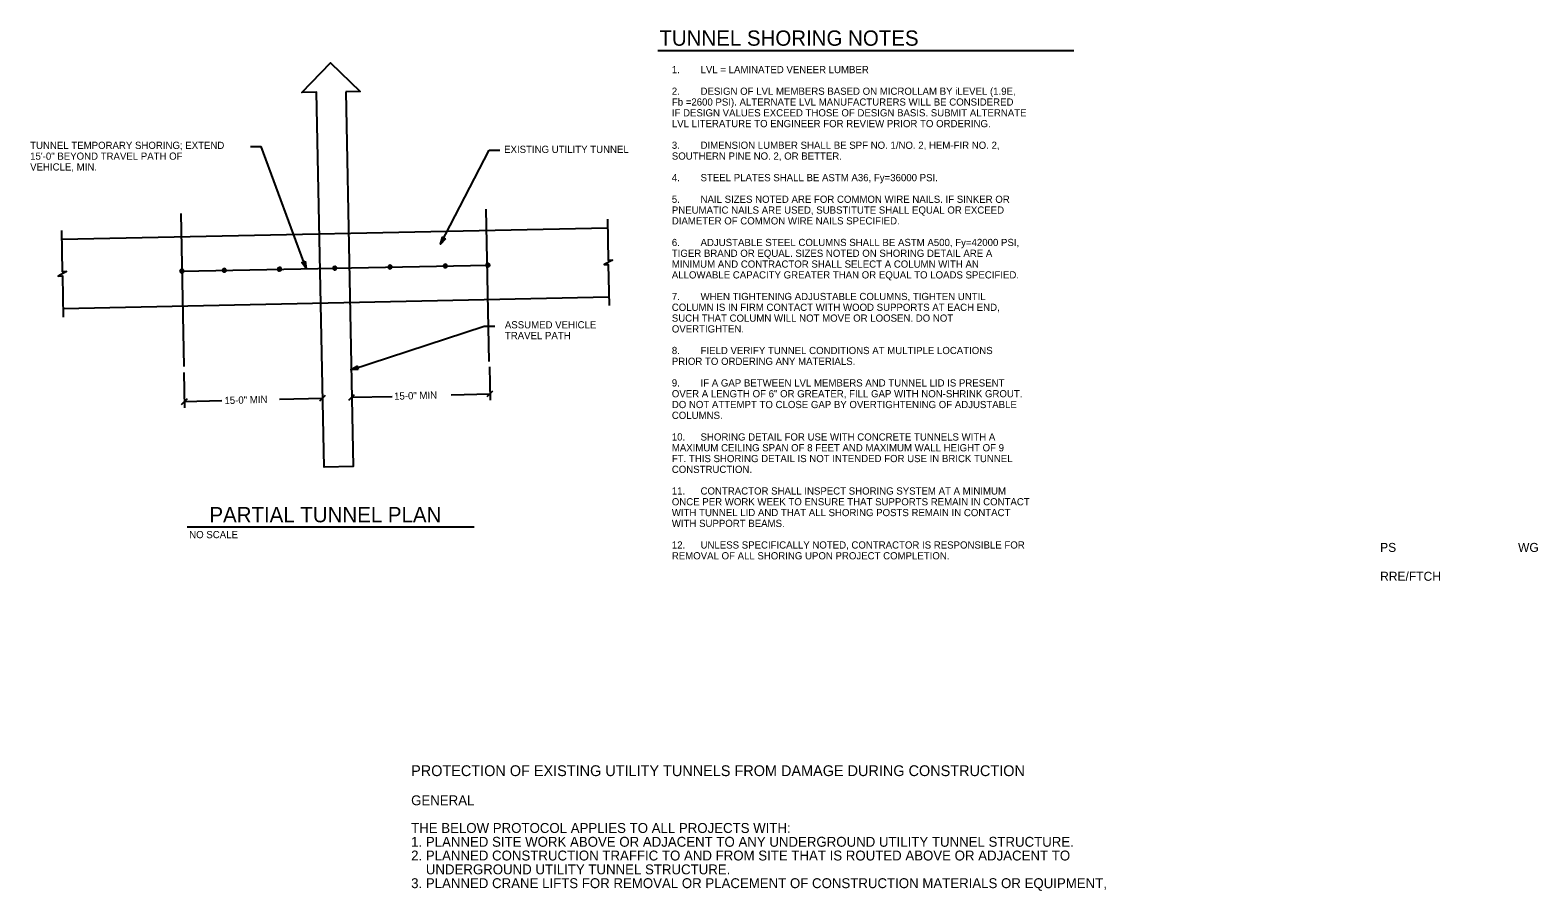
# Model space of a CAD drawing. Extents: x 10051 to 10282, y 10006 to 10178.
# Drawn here: x 10134.4 to 10274, y 10084.9 to 10164.6 of the extents above; entities that cross this region are included whole.
import ezdxf

# ---------------------------------------------------------------- set-up
doc = ezdxf.new("R2010")
doc.units = 0
for name, color, linetype in [('G-ANNO-CELL', 7, 'Continuous'), ('G-ANNO-TEXT', 7, 'Continuous'), ('G-DETL-LINE', 7, 'Continuous'), ('G-TITL-TEXT', 7, 'Continuous')]:
    doc.layers.add(name, color=color, linetype=linetype)

msp = doc.modelspace()

# ---------------------------------------------------------------- linework, layer by layer
at = {"layer": 'G-ANNO-CELL'}
for p, q in [((10192.53, 10162.71), (10231.05, 10162.71)), ((10148.96, 10118.6), (10175.54, 10118.6))]:
    msp.add_line(p, q, dxfattribs=at)
at = {"layer": 'G-ANNO-TEXT'}
for p, q in [((10154.81, 10153.83), (10155.81, 10153.83)), ((10159.96, 10142.51), (10155.81, 10153.83)), ((10172.42, 10144.76), (10176.91, 10153.49)), ((10176.91, 10153.49), (10177.91, 10153.49)), ((10148.36, 10147.6), (10148.64, 10133.45)), ((10176.93, 10133.92), (10176.65, 10148.02)), ((10164.1, 10133.13), (10176.44, 10137.17)), ((10176.44, 10137.17), (10177.44, 10137.17)), ((10176.94, 10133.42), (10177, 10130.34)), ((10148.65, 10132.9), (10148.71, 10129.63)), ((10148.44, 10129.95), (10148.97, 10130.48)), ((10157.51, 10130.43), (10161.5, 10130.53)), ((10161.23, 10130.27), (10161.76, 10130.8)), ((10163.93, 10130.34), (10164.46, 10130.87)), ((10164.19, 10130.6), (10167.93, 10130.69)), ((10173.4, 10130.83), (10176.99, 10130.92)), ((10176.73, 10130.66), (10177.26, 10131.19)), ((10148.7, 10130.21), (10152.17, 10130.3))]:
    msp.add_line(p, q, dxfattribs=at)
for points in [[(10172.88, 10145.27), (10172.42, 10144.76), (10172.58, 10145.42)], [(10159.89, 10143.19), (10159.96, 10142.51), (10159.57, 10143.08)], [(10164.78, 10133.18), (10164.1, 10133.13), (10164.68, 10133.49)]]:
    msp.add_lwpolyline(points, close=True, dxfattribs=at)
at = {"layer": 'G-DETL-LINE'}
msp.add_line((10148.46, 10142.28), (10176.75, 10142.84), dxfattribs=at)
for points in [[(10163.63, 10158.89), (10164.32, 10124.2), (10161.63, 10124.14), (10160.93, 10158.83), (10159.58, 10158.81), (10162.23, 10161.56), (10164.98, 10158.91), (10163.63, 10158.89)], [(10187.86, 10147.09), (10187.94, 10143.29), (10188.34, 10143.3), (10187.55, 10142.89), (10187.95, 10142.89), (10188.02, 10139.09)], [(10137.32, 10146.03), (10137.39, 10142.23), (10137.79, 10142.24), (10137, 10141.82), (10137.4, 10141.83), (10137.48, 10138.03)], [(10137.33, 10145.23), (10187.88, 10146.29)], [(10172.86, 10142.92), (10172.86, 10142.76), (10172.7, 10142.76)], [(10172.86, 10142.61), (10172.86, 10142.92), (10172.86, 10142.92)], [(10176.78, 10143), (10176.79, 10142.84), (10176.63, 10142.84)], [(10176.79, 10142.69), (10176.78, 10143), (10176.78, 10143)], [(10148.46, 10142.12), (10148.46, 10142.43), (10148.46, 10142.43)], [(10148.46, 10142.43), (10148.46, 10142.28), (10148.62, 10142.28)], [(10148.62, 10142.28), (10148.46, 10142.28), (10148.46, 10142.12)], [(10152.39, 10142.2), (10152.38, 10142.51), (10152.38, 10142.51)], [(10152.38, 10142.51), (10152.39, 10142.36), (10152.54, 10142.36)], [(10152.54, 10142.36), (10152.39, 10142.36), (10152.39, 10142.2)], [(10157.51, 10142.3), (10157.5, 10142.62), (10157.5, 10142.62)], [(10157.5, 10142.62), (10157.5, 10142.46), (10157.66, 10142.46)], [(10157.66, 10142.46), (10157.5, 10142.46), (10157.51, 10142.3)], [(10162.63, 10142.4), (10162.62, 10142.72), (10162.62, 10142.72)], [(10162.62, 10142.72), (10162.62, 10142.56), (10162.78, 10142.56)], [(10162.78, 10142.56), (10162.62, 10142.56), (10162.63, 10142.4)], [(10167.74, 10142.82), (10167.74, 10142.66), (10167.59, 10142.66)], [(10167.59, 10142.66), (10167.74, 10142.66), (10167.75, 10142.51)], [(10167.75, 10142.51), (10167.74, 10142.82), (10167.74, 10142.82)], [(10172.7, 10142.76), (10172.86, 10142.76), (10172.86, 10142.61)], [(10176.63, 10142.84), (10176.79, 10142.84), (10176.79, 10142.69)], [(10137.46, 10138.83), (10188.01, 10139.89)]]:
    msp.add_lwpolyline(points, dxfattribs=at)
for centre in [(10172.86, 10142.76), (10176.79, 10142.84), (10148.46, 10142.28), (10152.39, 10142.36), (10157.5, 10142.46), (10162.62, 10142.56), (10167.74, 10142.66)]:
    msp.add_circle(centre, 0.157, dxfattribs=at)
for centre, start, end in [((10172.86, 10142.76), 91.1419, 181.1419), ((10172.86, 10142.76), 1.1419, 91.1419), ((10176.79, 10142.84), 91.1419, 181.1419), ((10176.79, 10142.84), 1.1419, 91.1419), ((10148.46, 10142.28), 91.1419, 181.1419), ((10148.46, 10142.28), 181.1419, 271.1419), ((10148.46, 10142.28), 1.1419, 91.1419), ((10148.46, 10142.28), 271.1419, 1.1419), ((10152.39, 10142.36), 91.1419, 181.1419), ((10152.39, 10142.36), 181.1419, 271.1419), ((10152.39, 10142.36), 1.1419, 91.1419), ((10152.39, 10142.36), 271.1419, 1.1419), ((10157.5, 10142.46), 91.1419, 181.1419), ((10157.5, 10142.46), 181.1419, 271.1419), ((10157.5, 10142.46), 1.1419, 91.1419), ((10157.5, 10142.46), 271.1419, 1.1419), ((10162.62, 10142.56), 91.1419, 181.1419), ((10162.62, 10142.56), 181.1419, 271.1419), ((10162.62, 10142.56), 1.1419, 91.1419), ((10162.62, 10142.56), 271.1419, 1.1419), ((10167.74, 10142.66), 91.1419, 181.1419), ((10167.74, 10142.66), 181.1419, 271.1419), ((10167.74, 10142.66), 1.1419, 91.1419), ((10167.74, 10142.66), 271.1419, 1.1419), ((10172.86, 10142.76), 181.1419, 271.1419), ((10172.86, 10142.76), 271.1419, 1.1419), ((10176.79, 10142.84), 181.1419, 271.1419), ((10176.79, 10142.84), 271.1419, 1.1419)]:
    msp.add_arc(centre, 0.157, start, end, dxfattribs=at)

# ---------------------------------------------------------------- texts
at = {"layer": 'G-ANNO-CELL'}
for s, height, p in [('TUNNEL SHORING NOTES', 1.4167, (10192.68, 10163.14)), ('PARTIAL TUNNEL PLAN', 1.4167, (10151.01, 10119.03)), ('NO SCALE', 0.667, (10149.14, 10117.56))]:
    msp.add_text(s, height=height, dxfattribs=at).set_placement(p)
at = {"layer": 'G-ANNO-TEXT'}
for s, height, p in [('1.', 0.667, (10193.83, 10160.6)), ('LVL = LAMINATED VENEER LUMBER', 0.6667, (10196.49, 10160.6)), ('2.', 0.667, (10193.83, 10158.6)), ('Fb =2600 PSI). ALTERNATE LVL MANUFACTURERS WILL BE CONSIDERED ', 0.6667, (10193.83, 10157.6)), ('DESIGN OF LVL MEMBERS BASED ON MICROLLAM BY iLEVEL (1.9E, ', 0.6667, (10196.49, 10158.6)), ('IF DESIGN VALUES EXCEED THOSE OF DESIGN BASIS. SUBMIT ALTERNATE ', 0.6667, (10193.83, 10156.6)), ('LVL LITERATURE TO ENGINEER FOR REVIEW PRIOR TO ORDERING.', 0.6667, (10193.83, 10155.6)), ('TUNNEL TEMPORARY SHORING; EXTEND ', 0.6667, (10134.41, 10153.59)), ('3.', 0.667, (10193.83, 10153.6)), ('DIMENSION LUMBER SHALL BE SPF NO. 1/NO. 2, HEM-FIR NO. 2, ', 0.6667, (10196.49, 10153.6)), ('15\'-0" BEYOND TRAVEL PATH OF ', 0.6667, (10134.41, 10152.59)), ('EXISTING UTILITY TUNNEL', 0.6667, (10178.3, 10153.22)), ('SOUTHERN PINE NO. 2, OR BETTER.', 0.6667, (10193.83, 10152.6)), ('VEHICLE, MIN.', 0.6667, (10134.41, 10151.59)), ('STEEL PLATES SHALL BE ASTM A36, Fy=36000 PSI.', 0.6667, (10196.49, 10150.6)), ('4.', 0.667, (10193.83, 10150.6)), ('5.', 0.667, (10193.83, 10148.6)), ('NAIL SIZES NOTED ARE FOR COMMON WIRE NAILS. IF SINKER OR ', 0.6667, (10196.49, 10148.6)), ('PNEUMATIC NAILS ARE USED, SUBSTITUTE SHALL EQUAL OR EXCEED ', 0.6667, (10193.83, 10147.6)), ('DIAMETER OF COMMON WIRE NAILS SPECIFIED.', 0.6667, (10193.83, 10146.6)), ('6.', 0.667, (10193.83, 10144.6)), ('ADJUSTABLE STEEL COLUMNS SHALL BE ASTM A500, Fy=42000 PSI, ', 0.6667, (10196.49, 10144.6)), ('TIGER BRAND OR EQUAL. SIZES NOTED ON SHORING DETAIL ARE A ', 0.6667, (10193.83, 10143.6)), ('MINIMUM AND CONTRACTOR SHALL SELECT A COLUMN WITH AN ', 0.6667, (10193.83, 10142.6)), ('ALLOWABLE CAPACITY GREATER THAN OR EQUAL TO LOADS SPECIFIED.', 0.6667, (10193.83, 10141.6)), ('7.', 0.667, (10193.83, 10139.6)), ('WHEN TIGHTENING ADJUSTABLE COLUMNS, TIGHTEN UNTIL ', 0.6667, (10196.49, 10139.6)), ('COLUMN IS IN FIRM CONTACT WITH WOOD SUPPORTS AT EACH END, ', 0.6667, (10193.83, 10138.6)), ('ASSUMED VEHICLE', 0.6667, (10178.37, 10136.98)), ('SUCH THAT COLUMN WILL NOT MOVE OR LOOSEN. DO NOT ', 0.6667, (10193.83, 10137.6)), ('TRAVEL PATH', 0.6667, (10178.37, 10135.98)), ('OVERTIGHTEN.', 0.6667, (10193.83, 10136.6)), ('8.', 0.667, (10193.83, 10134.6)), ('FIELD VERIFY TUNNEL CONDITIONS AT MULTIPLE LOCATIONS ', 0.6667, (10196.49, 10134.6)), ('PRIOR TO ORDERING ANY MATERIALS.', 0.6667, (10193.83, 10133.6)), ('9.', 0.667, (10193.83, 10131.6)), ('IF A GAP BETWEEN LVL MEMBERS AND TUNNEL LID IS PRESENT ', 0.6667, (10196.49, 10131.6)), ('OVER A LENGTH OF 6" OR GREATER, FILL GAP WITH NON-SHRINK GROUT. ', 0.6667, (10193.83, 10130.6)), ('COLUMNS.', 0.667, (10193.83, 10128.6)), ('DO NOT ATTEMPT TO CLOSE GAP BY OVERTIGHTENING OF ADJUSTABLE ', 0.6667, (10193.83, 10129.6)), ('10.', 0.667, (10193.83, 10126.6)), ('MAXIMUM CEILING SPAN OF 8 FEET AND MAXIMUM WALL HEIGHT OF 9 ', 0.6667, (10193.83, 10125.6)), ('SHORING DETAIL FOR USE WITH CONCRETE TUNNELS WITH A ', 0.6667, (10196.49, 10126.6)), ('FT. THIS SHORING DETAIL IS NOT INTENDED FOR USE IN BRICK TUNNEL ', 0.6667, (10193.83, 10124.6)), ('CONSTRUCTION.', 0.6667, (10193.83, 10123.6)), ('11.', 0.667, (10193.83, 10121.6)), ('CONTRACTOR SHALL INSPECT SHORING SYSTEM AT A MINIMUM ', 0.6667, (10196.49, 10121.6)), ('ONCE PER WORK WEEK TO ENSURE THAT SUPPORTS REMAIN IN CONTACT ', 0.6667, (10193.83, 10120.6)), ('WITH TUNNEL LID AND THAT ALL SHORING POSTS REMAIN IN CONTACT ', 0.6667, (10193.83, 10119.6)), ('WITH SUPPORT BEAMS.', 0.6667, (10193.83, 10118.6)), ('12.', 0.667, (10193.83, 10116.6)), ('UNLESS SPECIFICALLY NOTED, CONTRACTOR IS RESPONSIBLE FOR ', 0.6667, (10196.49, 10116.6)), ('REMOVAL OF ALL SHORING UPON PROJECT COMPLETION.', 0.6667, (10193.83, 10115.6)), ('PROTECTION OF EXISTING UTILITY TUNNELS FROM DAMAGE DURING CONSTRUCTION', 1, (10169.69, 10095.54)), ('GENERAL', 0.917, (10169.69, 10092.84)), ('THE BELOW PROTOCOL APPLIES TO ALL PROJECTS WITH:', 0.9167, (10169.69, 10090.28)), ('1. PLANNED SITE WORK ABOVE OR ADJACENT TO ANY UNDERGROUND UTILITY TUNNEL STRUCTURE.', 0.9167, (10169.69, 10089)), ('2. PLANNED CONSTRUCTION TRAFFIC TO AND FROM SITE THAT IS ROUTED ABOVE OR ADJACENT TO ', 0.9167, (10169.69, 10087.73)), ('    UNDERGROUND UTILITY TUNNEL STRUCTURE.  ', 0.9167, (10169.69, 10086.45)), ('3. PLANNED CRANE LIFTS FOR REMOVAL OR PLACEMENT OF CONSTRUCTION MATERIALS OR EQUIPMENT, ', 0.9167, (10169.69, 10085.17))]:
    msp.add_text(s, height=height, dxfattribs=at).set_placement(p)
for p in [(10152.41, 10129.97), (10168.12, 10130.37)]:
    msp.add_text('15-0" MIN', height=0.667, rotation=1.6978, dxfattribs=at).set_placement(p)
at = {"layer": 'G-TITL-TEXT'}
for s, p in [('PS ', (10259.42, 10116.29)), ('WG ', (10272.19, 10116.29)), ('RRE/FTCH  ', (10259.42, 10113.62))]:
    msp.add_text(s, height=0.833, dxfattribs=at).set_placement(p)

doc.saveas('drawing.dxf')
